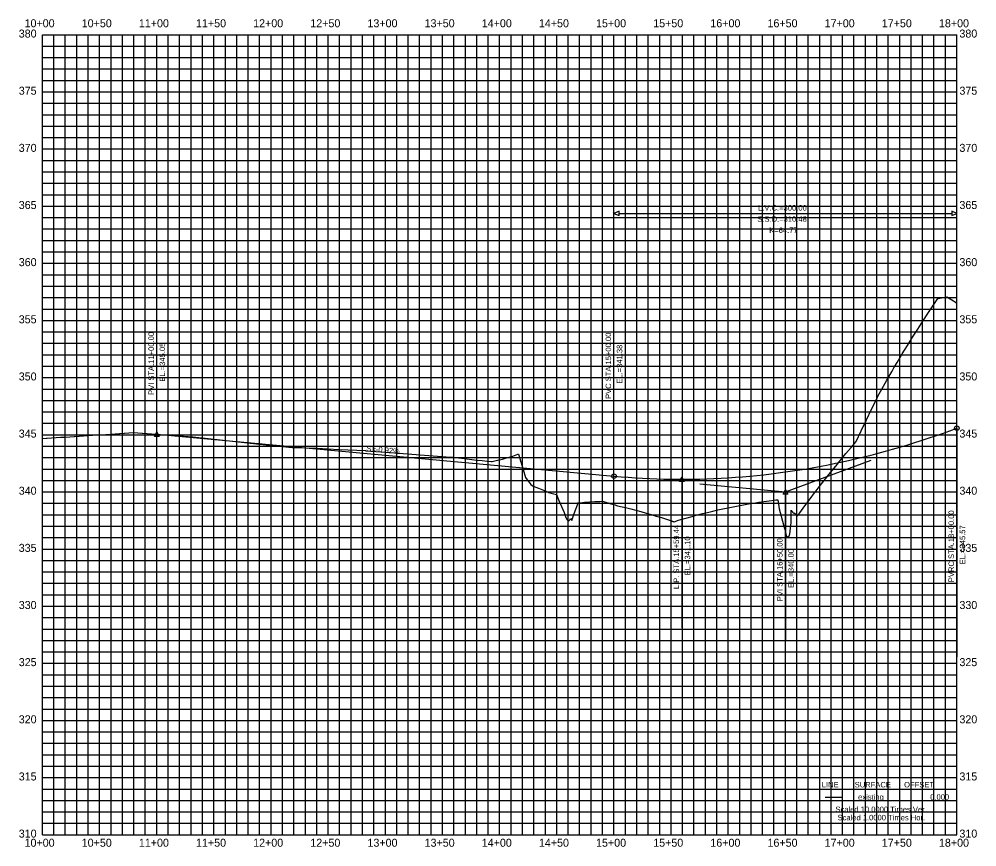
# Model space of a CAD drawing. Extents: x -797 to 1040, y -6256 to -5532.
# Drawn here: x -797 to 41, y -6256 to -5532 of the extents above; entities that cross this region are included whole.
import ezdxf

# ---------------------------------------------------------------- set-up
doc = ezdxf.new("R2010")
doc.units = 0
for name, color, linetype in [('CT_Pro_Grid_Frame', 7, 'Continuous'), ('CT_Pro_screen_Major', 7, 'Continuous'), ('CT_Pro_screen_Minor', 7, 'Continuous'), ('HM-SMOD-USR DEF1', 7, 'Continuous'), ('HR-GMSC-HOR_VER ALN', 7, 'Continuous'), ('HR-GMSC-PVCPVT SYMB', 7, 'Continuous'), ('HR-GPRO-PVCPVIPVT LDR', 7, 'Continuous'), ('HR-GPRO-PVCPVT TXT', 7, 'Continuous'), ('HR-GPRO-PVI SYMB', 7, 'Continuous'), ('HR-GPRO-PVI TXT', 7, 'Continuous'), ('HR-GPRO-STA_ELEV GRID TXT', 7, 'Continuous'), ('HR-GPRO-TAN GRADE TXT', 7, 'Continuous')]:
    doc.layers.add(name, color=color, linetype=linetype)

msp = doc.modelspace()

# ---------------------------------------------------------------- linework, layer by layer
at = {"layer": 'CT_Pro_Grid_Frame'}
for p, q in [((-776.38, -5545.62), (23.62, -5545.62)), ((-776.38, -6245.62), (-776.38, -5545.62)), ((23.62, -6245.62), (23.62, -5545.62)), ((-776.38, -6245.62), (23.62, -6245.62))]:
    msp.add_line(p, q, dxfattribs=at)
at = {"layer": 'CT_Pro_screen_Major'}
for p, q in [((-726.38, -6245.62), (-726.38, -5545.62)), ((-676.38, -6245.62), (-676.38, -5545.62)), ((-626.38, -6245.62), (-626.38, -5545.62)), ((-576.38, -6245.62), (-576.38, -5545.62)), ((-526.38, -6245.62), (-526.38, -5545.62)), ((-476.38, -6245.62), (-476.38, -5545.62)), ((-426.38, -6245.62), (-426.38, -5545.62)), ((-376.38, -6245.62), (-376.38, -5545.62)), ((-326.38, -6245.62), (-326.38, -5545.62)), ((-276.38, -6245.62), (-276.38, -5545.62)), ((-226.38, -6245.62), (-226.38, -5545.62)), ((-176.38, -6245.62), (-176.38, -5545.62)), ((-126.38, -6245.62), (-126.38, -5545.62)), ((-76.38, -6245.62), (-76.38, -5545.62)), ((-26.38, -6245.62), (-26.38, -5545.62)), ((-776.38, -5595.62), (23.62, -5595.62)), ((-776.38, -5645.62), (23.62, -5645.62)), ((-776.38, -5695.62), (23.62, -5695.62)), ((-776.38, -5745.62), (23.62, -5745.62)), ((-776.38, -5795.62), (23.62, -5795.62)), ((-776.38, -5845.62), (23.62, -5845.62)), ((-776.38, -5895.62), (23.62, -5895.62)), ((-776.38, -5945.62), (23.62, -5945.62)), ((-776.38, -5995.62), (23.62, -5995.62)), ((-776.38, -6045.62), (23.62, -6045.62)), ((-776.38, -6095.62), (23.62, -6095.62)), ((-776.38, -6145.62), (23.62, -6145.62)), ((-776.38, -6195.62), (23.62, -6195.62))]:
    msp.add_line(p, q, dxfattribs=at)
at = {"layer": 'CT_Pro_screen_Minor'}
for p, q in [((-766.38, -6245.62), (-766.38, -5545.62)), ((-756.38, -6245.62), (-756.38, -5545.62)), ((-746.38, -6245.62), (-746.38, -5545.62)), ((-736.38, -6245.62), (-736.38, -5545.62)), ((-716.38, -6245.62), (-716.38, -5545.62)), ((-706.38, -6245.62), (-706.38, -5545.62)), ((-696.38, -6245.62), (-696.38, -5545.62)), ((-686.38, -6245.62), (-686.38, -5545.62)), ((-666.38, -6245.62), (-666.38, -5545.62)), ((-656.38, -6245.62), (-656.38, -5545.62)), ((-646.38, -6245.62), (-646.38, -5545.62)), ((-636.38, -6245.62), (-636.38, -5545.62)), ((-616.38, -6245.62), (-616.38, -5545.62)), ((-606.38, -6245.62), (-606.38, -5545.62)), ((-596.38, -6245.62), (-596.38, -5545.62)), ((-586.38, -6245.62), (-586.38, -5545.62)), ((-566.38, -6245.62), (-566.38, -5545.62)), ((-556.38, -6245.62), (-556.38, -5545.62)), ((-546.38, -6245.62), (-546.38, -5545.62)), ((-536.38, -6245.62), (-536.38, -5545.62)), ((-516.38, -6245.62), (-516.38, -5545.62)), ((-506.38, -6245.62), (-506.38, -5545.62)), ((-496.38, -6245.62), (-496.38, -5545.62)), ((-486.38, -6245.62), (-486.38, -5545.62)), ((-466.38, -6245.62), (-466.38, -5545.62)), ((-456.38, -6245.62), (-456.38, -5545.62)), ((-446.38, -6245.62), (-446.38, -5545.62)), ((-436.38, -6245.62), (-436.38, -5545.62)), ((-416.38, -6245.62), (-416.38, -5545.62)), ((-406.38, -6245.62), (-406.38, -5545.62)), ((-396.38, -6245.62), (-396.38, -5545.62)), ((-386.38, -6245.62), (-386.38, -5545.62)), ((-366.38, -6245.62), (-366.38, -5545.62)), ((-356.38, -6245.62), (-356.38, -5545.62)), ((-346.38, -6245.62), (-346.38, -5545.62)), ((-336.38, -6245.62), (-336.38, -5545.62)), ((-316.38, -6245.62), (-316.38, -5545.62)), ((-306.38, -6245.62), (-306.38, -5545.62)), ((-296.38, -6245.62), (-296.38, -5545.62)), ((-286.38, -6245.62), (-286.38, -5545.62)), ((-266.38, -6245.62), (-266.38, -5545.62)), ((-256.38, -6245.62), (-256.38, -5545.62)), ((-246.38, -6245.62), (-246.38, -5545.62)), ((-236.38, -6245.62), (-236.38, -5545.62)), ((-216.38, -6245.62), (-216.38, -5545.62)), ((-206.38, -6245.62), (-206.38, -5545.62)), ((-196.38, -6245.62), (-196.38, -5545.62)), ((-186.38, -6245.62), (-186.38, -5545.62)), ((-166.38, -6245.62), (-166.38, -5545.62)), ((-156.38, -6245.62), (-156.38, -5545.62)), ((-146.38, -6245.62), (-146.38, -5545.62)), ((-136.38, -6245.62), (-136.38, -5545.62)), ((-116.38, -6245.62), (-116.38, -5545.62)), ((-106.38, -6245.62), (-106.38, -5545.62)), ((-96.38, -6245.62), (-96.38, -5545.62)), ((-86.38, -6245.62), (-86.38, -5545.62)), ((-66.38, -6245.62), (-66.38, -5545.62)), ((-56.38, -6245.62), (-56.38, -5545.62)), ((-46.38, -6245.62), (-46.38, -5545.62)), ((-36.38, -6245.62), (-36.38, -5545.62)), ((-16.38, -6245.62), (-16.38, -5545.62)), ((-6.38, -6245.62), (-6.38, -5545.62)), ((3.62, -6245.62), (3.62, -5545.62)), ((13.62, -6245.62), (13.62, -5545.62)), ((-776.38, -5555.62), (23.62, -5555.62)), ((-776.38, -5565.62), (23.62, -5565.62)), ((-776.38, -5575.62), (23.62, -5575.62)), ((-776.38, -5585.62), (23.62, -5585.62)), ((-776.38, -5605.62), (23.62, -5605.62)), ((-776.38, -5615.62), (23.62, -5615.62)), ((-776.38, -5625.62), (23.62, -5625.62)), ((-776.38, -5635.62), (23.62, -5635.62)), ((-776.38, -5655.62), (23.62, -5655.62)), ((-776.38, -5665.62), (23.62, -5665.62)), ((-776.38, -5675.62), (23.62, -5675.62)), ((-776.38, -5685.62), (23.62, -5685.62)), ((-776.38, -5705.62), (23.62, -5705.62)), ((-776.38, -5715.62), (23.62, -5715.62)), ((-776.38, -5725.62), (23.62, -5725.62)), ((-776.38, -5735.62), (23.62, -5735.62)), ((-776.38, -5755.62), (23.62, -5755.62)), ((-776.38, -5765.62), (23.62, -5765.62)), ((-776.38, -5775.62), (23.62, -5775.62)), ((-776.38, -5785.62), (23.62, -5785.62)), ((-776.38, -5805.62), (23.62, -5805.62)), ((-776.38, -5815.62), (23.62, -5815.62)), ((-776.38, -5825.62), (23.62, -5825.62)), ((-776.38, -5835.62), (23.62, -5835.62)), ((-776.38, -5855.62), (23.62, -5855.62)), ((-776.38, -5865.62), (23.62, -5865.62)), ((-776.38, -5875.62), (23.62, -5875.62)), ((-776.38, -5885.62), (23.62, -5885.62)), ((-776.38, -5905.62), (23.62, -5905.62)), ((-776.38, -5915.62), (23.62, -5915.62)), ((-776.38, -5925.62), (23.62, -5925.62)), ((-776.38, -5935.62), (23.62, -5935.62)), ((-776.38, -5955.62), (23.62, -5955.62)), ((-776.38, -5965.62), (23.62, -5965.62)), ((-776.38, -5975.62), (23.62, -5975.62)), ((-776.38, -5985.62), (23.62, -5985.62)), ((-776.38, -6005.62), (23.62, -6005.62)), ((-776.38, -6015.62), (23.62, -6015.62)), ((-776.38, -6025.62), (23.62, -6025.62)), ((-776.38, -6035.62), (23.62, -6035.62)), ((-776.38, -6055.62), (23.62, -6055.62)), ((-776.38, -6065.62), (23.62, -6065.62)), ((-776.38, -6075.62), (23.62, -6075.62)), ((-776.38, -6085.62), (23.62, -6085.62)), ((-776.38, -6105.62), (23.62, -6105.62)), ((-776.38, -6115.62), (23.62, -6115.62)), ((-776.38, -6125.62), (23.62, -6125.62)), ((-776.38, -6135.62), (23.62, -6135.62)), ((-776.38, -6155.62), (23.62, -6155.62)), ((-776.38, -6165.62), (23.62, -6165.62)), ((-776.38, -6175.62), (23.62, -6175.62)), ((-776.38, -6185.62), (23.62, -6185.62)), ((-776.38, -6205.62), (23.62, -6205.62)), ((-776.38, -6215.62), (23.62, -6215.62)), ((-776.38, -6225.62), (23.62, -6225.62)), ((-776.38, -6235.62), (23.62, -6235.62))]:
    msp.add_line(p, q, dxfattribs=at)
at = {"layer": 'HM-SMOD-USR DEF1'}
msp.add_line((-91.58, -6212.62), (-77.18, -6212.62), dxfattribs=at)
msp.add_lwpolyline([(-776.38, -5898.9), (-776.36, -5898.9), (-776.32, -5898.9), (-772.96, -5898.64), (-772.37, -5898.61), (-772.36, -5898.61), (-768.4, -5898.36), (-768.36, -5898.36), (-764.43, -5898.12), (-764.35, -5898.11), (-760.46, -5897.87), (-760.35, -5897.87), (-756.49, -5897.63), (-756.35, -5897.62), (-752.53, -5897.38), (-752.36, -5897.37), (-748.56, -5897.13), (-748.38, -5897.12), (-744.6, -5896.88), (-744.39, -5896.87), (-740.63, -5896.63), (-740.41, -5896.61), (-736.67, -5896.37), (-736.44, -5896.36), (-732.7, -5896.12), (-732.46, -5896.1), (-728.74, -5895.86), (-728.49, -5895.85), (-724.77, -5895.61), (-724.52, -5895.59), (-720.8, -5895.35), (-720.56, -5895.33), (-716.84, -5895.09), (-716.59, -5895.07), (-712.87, -5894.82), (-712.63, -5894.81), (-708.9, -5894.56), (-708.67, -5894.54), (-704.92, -5894.29), (-704.71, -5894.28), (-700.95, -5894.03), (-700.75, -5894.01), (-696.97, -5893.76), (-696.79, -5893.77), (-692.99, -5894.03), (-692.83, -5894.04), (-689.01, -5894.3), (-688.88, -5894.31), (-685.02, -5894.57), (-684.92, -5894.57), (-681.03, -5894.83), (-680.96, -5894.84), (-677.04, -5895.1), (-677.01, -5895.1), (-673.63, -5895.33), (-673.05, -5895.37), (-673.04, -5895.37), (-669.08, -5895.69), (-669.02, -5895.69), (-665.09, -5896.01), (-661.26, -5896.31), (-661.09, -5896.32), (-657.3, -5896.63), (-657.08, -5896.64), (-653.34, -5896.95), (-653.04, -5896.97), (-649.35, -5897.27), (-648.99, -5897.29), (-645.36, -5897.59), (-644.92, -5897.61), (-604.98, -5901.81), (-594.73, -5903.15), (-557.8, -5906.73), (-536.18, -5907.52), (-516.88, -5908.44), (-493.89, -5909.48), (-493.34, -5909.7), (-475.88, -5910.77), (-419.32, -5915.22), (-416.95, -5915.38), (-405.24, -5916.73), (-400.76, -5917.25), (-396.27, -5917.75), (-391.79, -5918.26), (-387.3, -5918.76), (-383.84, -5919.14), (-382.82, -5918.95), (-378.34, -5917.97), (-373.85, -5916.87), (-369.37, -5915.63), (-364.88, -5914.26), (-360.4, -5912.76), (-359.82, -5912.54), (-355.92, -5925.99), (-353.89, -5933.19), (-351.43, -5936.22), (-349.88, -5938.13), (-349.06, -5939.28), (-347.88, -5940.18), (-346.95, -5940.54), (-342.46, -5942.34), (-337.98, -5944.21), (-333.95, -5945.95), (-333.5, -5946.07), (-329.01, -5947.33), (-326.73, -5948.01), (-324.53, -5953.16), (-320.04, -5963.72), (-318.92, -5966.36), (-318.74, -5967.19), (-317.5, -5969.78), (-316.7, -5970.54), (-316.26, -5971.13), (-315.56, -5970.43), (-315.38, -5970.25), (-314.69, -5969.91), (-314.54, -5968.79), (-313.32, -5970.82), (-311.08, -5964.53), (-307.51, -5954.53), (-306.59, -5954.85), (-305.91, -5955.1), (-302.11, -5954.76), (-297.62, -5954.42), (-293.14, -5954.15), (-288.66, -5953.94), (-286.4, -5953.86), (-284.62, -5954.37), (-284.17, -5954.5), (-283.51, -5954.69), (-282.8, -5954.9), (-281.45, -5955.29), (-280.05, -5955.69), (-279.69, -5955.79), (-279.17, -5955.95), (-277.53, -5956.43), (-276.76, -5956.65), (-275.34, -5957.07), (-275.2, -5957.11), (-274.04, -5957.46), (-273.23, -5957.7), (-271.74, -5958.15), (-270.72, -5958.37), (-266.24, -5959.43), (-261.75, -5960.53), (-257.27, -5961.68), (-252.78, -5962.88), (-248.3, -5964.12), (-243.82, -5965.42), (-239.33, -5966.76), (-234.85, -5968.15), (-230.36, -5969.58), (-226.06, -5971), (-225.88, -5971.07), (-225.75, -5971.12), (-225.61, -5971.17), (-225.42, -5971.25), (-225.24, -5971.31), (-225.16, -5971.35), (-225, -5971.4), (-224.92, -5971.43), (-224.82, -5971.47), (-224.73, -5971.5), (-224.69, -5971.52), (-224.62, -5971.54), (-224.53, -5971.57), (-224.45, -5971.6), (-224.41, -5971.61), (-224.34, -5971.63), (-224.3, -5971.64), (-224.25, -5971.66), (-224.2, -5971.67), (-224.18, -5971.68), (-224.13, -5971.69), (-224.11, -5971.7), (-224.07, -5971.7), (-224.03, -5971.72), (-224.01, -5971.72), (-223.98, -5971.73), (-223.93, -5971.74), (-223.88, -5971.75), (-223.85, -5971.75), (-223.82, -5971.76), (-223.78, -5971.77), (-223.77, -5971.77), (-223.73, -5971.77), (-223.72, -5971.78), (-223.69, -5971.78), (-223.66, -5971.78), (-223.64, -5971.78), (-223.62, -5971.79), (-221.4, -5970.93), (-220.83, -5970.71), (-216.91, -5969.56), (-212.43, -5968.27), (-207.94, -5967.03), (-203.46, -5965.83), (-198.98, -5964.67), (-194.49, -5963.55), (-190.01, -5962.47), (-185.52, -5961.44), (-181.04, -5960.45), (-176.56, -5959.5), (-172.07, -5958.59), (-167.59, -5957.72), (-163.1, -5956.9), (-158.62, -5956.11), (-154.14, -5955.38), (-149.65, -5954.68), (-145.17, -5954.02), (-140.68, -5953.41), (-136.2, -5952.84), (-134.64, -5952.66), (-133.14, -5952.51), (-132.25, -5958.28), (-131.72, -5960.34), (-127.23, -5977.71), (-125.47, -5984.54), (-124.52, -5984.92), (-123.87, -5984.72), (-123.1, -5984.1), (-122.75, -5983.36), (-122.37, -5982.57), (-121.44, -5972.34), (-121.35, -5961.76), (-121.31, -5961.81), (-121.1, -5962.09), (-120.88, -5962.35), (-120.67, -5962.62), (-120.45, -5962.88), (-120.24, -5963.13), (-120.03, -5963.37), (-119.82, -5963.61), (-119.61, -5963.84), (-119.41, -5964.07), (-119.21, -5964.29), (-119.01, -5964.5), (-118.67, -5963.95), (-118.47, -5964.15), (-118.28, -5964.35), (-118.26, -5964.37), (-118.08, -5964.55), (-117.89, -5964.73), (-117.71, -5964.91), (-117.53, -5965.09), (-117.35, -5965.25), (-117.17, -5965.41), (-117, -5965.56), (-116.84, -5965.7), (-116.68, -5965.83), (-116.53, -5965.96), (-116.38, -5966.08), (-116.23, -5966.15), (-116.09, -5966.22), (-115.96, -5966.28), (-115.83, -5966.33), (-115.71, -5966.38), (-115.59, -5966.42), (-113.78, -5963.89), (-109.3, -5957.73), (-104.81, -5951.65), (-100.89, -5946.41), (-100.59, -5946.27), (-100.33, -5945.92), (-95.84, -5940.06), (-91.36, -5934.3), (-86.88, -5928.62), (-82.39, -5923.02), (-77.91, -5917.52), (-73.42, -5912.11), (-68.94, -5906.79), (-64.46, -5901.56), (-64.34, -5901.43), (-59.97, -5892.15), (-55.49, -5882.72), (-51, -5873.39), (-46.52, -5864.17), (-45.47, -5862.03), (-42.04, -5855.85), (-37.55, -5847.89), (-33.07, -5840.05), (-31.41, -5837.19), (-28.58, -5832.41), (-24.1, -5824.94), (-19.62, -5817.6), (-15.13, -5810.37), (-10.65, -5803.27), (-6.16, -5796.28), (-1.68, -5789.42), (2.8, -5782.69), (7.11, -5776.34), (7.29, -5776.31), (11.77, -5775.46), (14.76, -5774.91), (16.26, -5775.83), (20.74, -5778.58), (22.41, -5779.59), (23.62, -5780.55)], dxfattribs=at)
at = {"layer": 'HR-GMSC-HOR_VER ALN'}
msp.add_line((-676.38, -5895.14), (-276.38, -5931.85), dxfattribs=at)
msp.add_lwpolyline([(-276.38, -5931.85), (-270.13, -5932.4), (-263.88, -5932.88), (-257.63, -5933.3), (-251.38, -5933.66), (-245.13, -5933.97), (-238.88, -5934.21), (-232.63, -5934.39), (-226.38, -5934.51), (-220.13, -5934.57), (-213.88, -5934.57), (-207.63, -5934.51), (-201.38, -5934.39), (-195.13, -5934.21), (-188.88, -5933.97), (-182.63, -5933.67), (-176.38, -5933.31), (-170.13, -5932.89), (-163.88, -5932.41), (-157.63, -5931.86), (-151.38, -5931.26), (-145.13, -5930.6), (-138.88, -5929.88), (-132.63, -5929.09), (-120.13, -5927.34), (-113.88, -5926.38), (-107.63, -5925.35), (-101.38, -5924.27), (-95.13, -5923.12), (-88.88, -5921.92), (-82.63, -5920.65), (-76.38, -5919.33), (-70.13, -5917.94), (-63.88, -5916.49), (-57.63, -5914.99), (-51.38, -5913.42), (-45.13, -5911.79), (-38.88, -5910.1), (-32.63, -5908.35), (-26.38, -5906.55), (-20.13, -5904.68), (-13.88, -5902.75), (-7.63, -5900.76), (-1.38, -5898.71), (4.87, -5896.6), (11.12, -5894.43), (17.37, -5892.19), (23.62, -5889.9)], dxfattribs=at)
at = {"layer": 'HR-GMSC-PVCPVT SYMB'}
for centre in [(23.62, -5889.9), (-276.38, -5931.85)]:
    msp.add_circle(centre, 2, dxfattribs=at)
at = {"layer": 'HR-GPRO-PVCPVIPVT LDR'}
for p, q in [((-276.38, -5931.85), (-276.38, -5689.9)), ((23.62, -5889.9), (23.62, -5689.9)), ((-276.38, -5931.85), (-276.38, -5731.85)), ((-676.38, -5895.14), (-676.38, -5765.14)), ((23.62, -5889.9), (23.62, -6089.9)), ((-126.38, -5945.62), (-51.38, -5917.76)), ((-216.94, -5934.58), (-216.94, -6064.58)), ((-201.38, -5938.73), (-126.38, -5945.62)), ((-126.38, -5945.62), (-126.38, -6075.62))]:
    msp.add_line(p, q, dxfattribs=at)
for points in [[(-276.38, -5702), (-271.94, -5703.84), (-271.94, -5700.16)], [(23.62, -5702), (19.19, -5700.16), (19.19, -5703.84)]]:
    msp.add_lwpolyline(points, close=True, dxfattribs=at)
msp.add_lwpolyline([(-271.94, -5702), (19.19, -5702)], dxfattribs=at)
at = {"layer": 'HR-GPRO-PVI SYMB'}
for points in [[(-676.38, -5893.14), (-674.38, -5897.14), (-678.38, -5897.14)], [(-216.94, -5932.58), (-214.94, -5936.58), (-218.94, -5936.58)], [(-126.38, -5943.62), (-124.38, -5947.62), (-128.38, -5947.62)]]:
    msp.add_lwpolyline(points, close=True, dxfattribs=at)

# ---------------------------------------------------------------- texts
at = {"layer": 'HM-SMOD-USR DEF1'}
msp.add_text('-', height=0.0001, dxfattribs=at).set_placement((-776.38, -6245.62))
at = {"layer": 'HR-GPRO-PVCPVT TXT'}
for s, p in [('L.V.C.=300.00', (-150.25, -5699.5)), ('S.S.D.=310.48', (-150.95, -5709.3)), ('K=64.77', (-140.56, -5719.1))]:
    msp.add_text(s, height=4.8, dxfattribs=at).set_placement(p)
for s, p in [('PVC STA.15+00.00', (-278.88, -5864.32)), ('EL.=341.38', (-269.08, -5850.96)), ('PVRC STA.18+00.00', (21.12, -6024.64)), ('EL.=345.57', (30.92, -6008.96))]:
    msp.add_text(s, height=4.8, rotation=90, dxfattribs=at).set_placement(p)
at = {"layer": 'HR-GPRO-PVI TXT'}
for s, p in [('PVI STA.11+00.00', (-678.88, -5860.8)), ('EL.=345.05', (-669.08, -5849.2)), ('L.P. STA.15+59.44', (-219.44, -6030.73)), ('EL.=341.10', (-209.64, -6018.64)), ('PVI STA.16+50.00', (-128.88, -6041.28)), ('EL.=340.00', (-119.08, -6029.68))]:
    msp.add_text(s, height=4.8, rotation=90, dxfattribs=at).set_placement(p)
at = {"layer": 'HR-GPRO-STA_ELEV GRID TXT'}
for s, height, p in [('10+00', 7, (-792.04, -5539.12)), ('10+50', 7, (-742.04, -5539.12)), ('11+00', 7, (-692.04, -5539.12)), ('11+50', 7, (-642.04, -5539.12)), ('12+00', 7, (-592.04, -5539.12)), ('12+50', 7, (-542.04, -5539.12)), ('13+00', 7, (-492.04, -5539.12)), ('13+50', 7, (-442.04, -5539.12)), ('14+00', 7, (-392.04, -5539.12)), ('14+50', 7, (-342.04, -5539.12)), ('15+00', 7, (-292.04, -5539.12)), ('15+50', 7, (-242.04, -5539.12)), ('16+00', 7, (-192.04, -5539.12)), ('16+50', 7, (-142.04, -5539.12)), ('17+00', 7, (-92.04, -5539.12)), ('17+50', 7, (-42.04, -5539.12)), ('18+00', 7, (7.96, -5539.12)), ('380', 7, (-797.13, -5548.12)), ('380', 7, (-797.13, -5548.12)), ('380', 7, (25.87, -5548.12)), ('380', 7, (25.87, -5548.12)), ('375', 7, (-797.13, -5598.12)), ('375', 7, (25.87, -5598.12)), ('370', 7, (-797.13, -5648.12)), ('370', 7, (25.87, -5648.12)), ('365', 7, (-797.13, -5698.12)), ('365', 7, (25.87, -5698.12)), ('360', 7, (-797.13, -5748.12)), ('360', 7, (25.87, -5748.12)), ('355', 7, (-797.13, -5798.12)), ('355', 7, (25.87, -5798.12)), ('350', 7, (-797.13, -5848.12)), ('350', 7, (25.87, -5848.12)), ('345', 7, (-797.13, -5898.12)), ('345', 7, (25.87, -5898.12)), ('340', 7, (-797.13, -5948.12)), ('340', 7, (25.87, -5948.12)), ('335', 7, (-797.13, -5998.12)), ('335', 7, (25.87, -5998.12)), ('330', 7, (-797.13, -6048.12)), ('330', 7, (25.87, -6048.12)), ('325', 7, (-797.13, -6098.12)), ('325', 7, (25.87, -6098.12)), ('320', 7, (-797.13, -6148.12)), ('320', 7, (25.87, -6148.12)), ('315', 7, (-797.13, -6198.12)), ('315', 7, (25.87, -6198.12)), (' LINE ', 4.8, (-96.38, -6204.22)), (' SURFACE ', 4.8, (-67.58, -6204.22)), (' OFFSET ', 4.8, (-24.38, -6204.22)), ('existing', 4.8, (-62.78, -6215.02)), ('0.000', 4.8, (0.3, -6215.02)), ('Scaled 10.0000 Times Ver.', 4.8, (-82.6, -6225.82)), ('Scaled 1.0000 Times Hor.', 4.8, (-80.78, -6233.02)), ('310', 7, (-797.13, -6248.12)), ('310', 7, (25.87, -6248.12)), ('10+00', 7, (-792.04, -6256.12)), ('10+50', 7, (-742.04, -6256.12)), ('11+00', 7, (-692.04, -6256.12)), ('11+50', 7, (-642.04, -6256.12)), ('12+00', 7, (-592.04, -6256.12)), ('12+50', 7, (-542.04, -6256.12)), ('13+00', 7, (-492.04, -6256.12)), ('13+50', 7, (-442.04, -6256.12)), ('14+00', 7, (-392.04, -6256.12)), ('14+50', 7, (-342.04, -6256.12)), ('15+00', 7, (-292.04, -6256.12)), ('15+50', 7, (-242.04, -6256.12)), ('16+00', 7, (-192.04, -6256.12)), ('16+50', 7, (-142.04, -6256.12)), ('17+00', 7, (-92.04, -6256.12)), ('17+50', 7, (-42.04, -6256.12)), ('18+00', 7, (7.96, -6256.12))]:
    msp.add_text(s, height=height, dxfattribs=at).set_placement(p)
at = {"layer": 'HR-GPRO-TAN GRADE TXT'}
msp.add_text('S=-0.92%', height=4.8, rotation=354.75648, dxfattribs=at).set_placement((-493.16, -5909.95))

doc.saveas('drawing.dxf')
